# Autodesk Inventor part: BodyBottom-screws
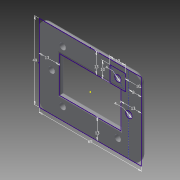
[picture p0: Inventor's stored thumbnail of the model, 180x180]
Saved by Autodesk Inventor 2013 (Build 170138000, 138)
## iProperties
Created: 2013-03
Part Number: BodyBottom-screws
Material: Generic
Document SubType Name: Modeling
Designer: frankenteddy
Density: 1 g/cm^3
Author: frankenteddy
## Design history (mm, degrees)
sketch "Sketch1"
  geometry: L1 (-32.5, 24.5)-(32.5, 24.5); L2 (32.5, 24.5)-(32.5, -24.5); L3 (32.5, -24.5)-(-32.5, -24.5); L4 (-32.5, -24.5)-(-32.5, 24.5); L5 (-19.5, 11.5)-(19.5, 11.5); L6 (19.5, 11.5)-(19.5, -11.5); L7 (19.5, -11.5)-(-19.5, -11.5); L8 (-19.5, -11.5)-(-19.5, 11.5); L9 (-24.5, 24.5)-(-24.5, -24.5); L10 (-22.5, 11.5)-(-12.5, 11.5); L11 (-12.5, 11.5)-(-12.5, 21.5); L12 (-12.5, 21.5)-(-22.5, 21.5); L13 (-22.5, 21.5)-(-22.5, 11.5); L14 (-22.5, 21.5)-(-12.5, 11.5); L15 (-22.5, 11.5)-(-12.5, 21.5); C1 r 2 at (-24.5, 0); C2 r 2 at (-17.5, 16.5); 4 further points
  constraints: 30 end point, 6 parallel, 4 midpoint, 4 perpendicular, 3 horizontal, 2 centre point, 2 point on line, 1 coincident, 1 collinear, 1 horizontal alignment, 1 vertical alignment
  dimensions: "d0" = 65 distance of L2.end L3.end; "d1" = 49 distance of L1.end L2.end; "d2" = 13 distance between parallel lines of L5 L1; "d3" = 13 distance between parallel lines of L4 L8; "d4" = 13 distance between parallel lines of L3 L7; "d5" = 13 distance between parallel lines of L2 L6; "d11" = 8 distance between parallel lines of L9 L4; "d12" = 4 diameter of C1; "d20" = 10 distance of L12.end L11.end; "d21" = 10 distance of L11.end L10.end; "d23" = 4 diameter of C2; "d26" = 10 distance between parallel lines of L4 L13
extrude "Extrusion1" new body sketch "Sketch1" distance "d6" = 3; taper "d7" = 0 deg
extrude "Extrusion2" cut sketch "Sketch1" distance "d8" = 3; taper "d9" = 0 deg
extrude "Extrusion4" cut sketch "Sketch1" distance "d18" = 3; taper "d19" = 0 deg
mirror "Mirror1"
extrude "Extrusion5" cut sketch "Sketch1" distance "d24" = 3; taper "d25" = 0 deg
mirror "Mirror4"
mirror "Mirror5"
fillet "Fillet1" dims "d27" = 5
fillet "Fillet2" dims "d28" = 2
fillet "Fillet3" dims "d29" = 1
body "Solid1"
